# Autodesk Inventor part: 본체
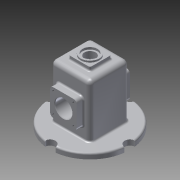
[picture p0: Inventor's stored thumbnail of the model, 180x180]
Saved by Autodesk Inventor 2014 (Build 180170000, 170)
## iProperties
Created: 2018-07
Part Number: 본체
Material: Aluminum 6061
Document SubType Name: Modeling
Designer: kh
Density: 2.71 g/cm^3
Appearance: Aluminum - Flat
Mass: 909.166 g
Surface Area: 1015.89 cm^2
Volume: 335.485 cm^3
Author: kh
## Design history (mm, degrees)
sketch "Sketch1"
  geometry: L1 (0, 0)-(0, 75); L2 (0, 0)-(75, 0); A1 r 75 centre (0, 0) between (0, 75) and (75, 0); 1 further point
  constraints: 4 end point, 2 point on circle, 1 centre point, 1 coincident, 1 perpendicular, 1 vertical
  dimensions: "d0" = 150 diameter of A1
extrude "Extrusion1" new body sketch "Sketch1" distance "d1" = 10; taper "d2" = 0 deg
sketch "Sketch2"
  geometry: L1 (0, 0)-(0, 75); L2 (0, 0)-(75, 0); A1 r 75 centre (0, 0) between (0, 75) and (75, 0) reference; 5 further points
  constraints: 4 end point, 2 point on circle, 1 coincident, 1 perpendicular, 1 vertical, 5 other
  dimensions: "d5" = 360 deg dimension on L1.start point (0, 75) (derived)
hole "Hole1" sketch "Sketch2" at (0, 75), (-75, 0), (0, -75), (75, 0) diameter "d7" = 20; stored, may be unused: countersink angle "d11" = 90 deg, drill point angle "d13" = 118 deg; dims "d8" = 6, "d9" = 4, "d10" = 2, "d12" = 8
sketch "Sketch3"
  geometry: L1 (65, 10)-(65, 0) reference; L2 (65, 0)-(-65, 0) reference; L3 (-65, 0)-(-65, 10) reference; L4 (-65, 10)-(65, 10) reference; L5 (0, 0)-(0, 10); L6 (-37, 0)-(37, 0); L7 (37, 0)-(37, 110); L8 (37, 110)-(-37, 110); L9 (-37, 110)-(-37, 0); L10 (-32, 0)-(32, 0); L11 (32, 0)-(32, 105); L12 (32, 105)-(-32, 105); L13 (-32, 105)-(-32, 0); 1 further point
  constraints: 18 end point, 4 midpoint, 4 parallel, 2 horizontal, 2 perpendicular, 2 other
  dimensions: "d14" = 110 distance between parallel lines of L8 L2; "d15" = 74 distance of L7.end L8.end; "d18" = 5 distance between parallel lines of L8 L12; "d19" = 5 distance between parallel lines of L9 L13
  node "Project Cut Edges1"
extrude "Extrusion2" join sketch "Sketch3" stored distance "d16" = 74; taper "d17" = 0 deg
extrude "Extrusion3" cut sketch "Sketch3" stored distance "d20" = 64; taper "d21" = 0 deg
sketch "Sketch4"
  geometry: L1 (65, 10)-(65, 0) reference; L2 (65, 0)-(32, 0) reference; L3 (32, 0)-(32, 105) reference; L4 (32, 105)-(-32, 105) reference; L5 (-32, 105)-(-32, 0) reference; L6 (-32, 0)-(-65, 0) reference; L7 (-65, 0)-(-65, 10) reference; L8 (-65, 10)-(-37, 10) reference; L9 (-37, 10)-(-37, 110) reference; L10 (-37, 110)-(37, 110) reference; L11 (37, 110)-(37, 10) reference; L12 (37, 10)-(65, 10) reference; L13 (-32, 80)-(-25, 77.452); L14 (-25, 77.452)-(-25, 55); L15 (-25, 55)-(-32, 55); L16 (-32, 55)-(-32, 80); 1 further point
  constraints: 8 end point, 2 perpendicular, 2 point on line, 1 collinear
  dimensions: "d22" = 55 distance from line of L14.end L6; "d23" = 50 diameter of L13.start L15; "d24" = 7 distance between parallel lines of L5 L14; "d25" = 110 deg angle of L5 L13
revolve "Revolution1" sketch "Sketch4" stored, may be unused: angle "d26" = 90 deg
mirror "Mirror1"
sketch "Sketch5"
  geometry: L1 (12, 20)-(62, 20); L2 (62, 20)-(62, 70); L3 (62, 70)-(12, 70); L4 (12, 70)-(12, 20); L5 (12, 20)-(62, 70); L6 (62, 20)-(12, 70); C1 r 25 at (37, 45) reference; 1 further point
  constraints: 12 end point, 2 midpoint, 2 parallel, 1 horizontal, 1 perpendicular
  dimensions: "d27" = 50 distance of L2.end L3.end; "d28" = 50 distance of L3.end L1.start
extrude "Extrusion4" join sketch "Sketch5" distance "d29" = 13; taper "d30" = 0 deg
mirror "Mirror2"
sketch "Sketch6"
  geometry: C1 r 22.452 at (37, 45) reference; C2 r 16 at (37, 45); 1 further point
  constraints: 1 centre point, 1 coincident
  dimensions: "d31" = 32 diameter of C2
extrude "Extrusion5" cut sketch "Sketch6" stored distance "d32" = 13; taper "d33" = 0 deg
sketch "Sketch7"
  geometry: L1 (0, 0)-(74, 0) reference; L2 (74, 74)-(74, 0) reference; L3 (0, 74)-(74, 74) reference; L4 (0, 0)-(0, 74) reference; L5 (17, 17)-(57, 17); L6 (57, 17)-(57, 57); L7 (57, 57)-(17, 57); L8 (17, 57)-(17, 17); L9 (17, 17)-(57, 57); L10 (57, 17)-(17, 57); 1 further point
  constraints: 12 end point, 2 midpoint, 2 parallel, 1 horizontal, 1 perpendicular
  dimensions: "d34" = 40 distance of L6.end L7.end; "d35" = 40 distance of L5.end L6.end
extrude "Extrusion6" join sketch "Sketch7" distance "d36" = 7; taper "d37" = 0 deg
sketch "Sketch8"
  geometry: C1 r 17.5 at (37, 37); 1 further point
  constraints: 1 centre point, 1 coincident
  dimensions: "d38" = 35 diameter of C1
extrude "Extrusion7" join sketch "Sketch8" distance "d39" = 3; taper "d40" = 0 deg
hole "Hole2" diameter "d43" = 21; stored, may be unused: countersink angle "d47" = 90 deg, drill point angle "d49" = 118 deg; dims "d41" = 10, "d42" = 10, "d44" = 6, "d45" = 28, "d46" = 4, "d48" = 8
fillet "Fillet1" dims "d50" = 6
fillet "Fillet2" dims "d51" = 6
sketch "Sketch9"
  geometry: L1 (64.567, -85.815)-(9.433, -85.815); L2 (9.433, -85.815)-(9.433, -74.185); L3 (9.433, -74.185)-(64.567, -74.185); L4 (64.567, -74.185)-(64.567, -85.815); L5 (64.567, -80)-(9.433, -80); L6 (37, -74.185)-(37, -85.815); L7 (19.5, -110)-(54.5, -110) reference; L8 (0, -100)-(0, 0) reference; 2 further points
  constraints: 5 midpoint, 4 end point, 2 other
  dimensions: "d52" = 30 distance from line of L7 point (37, -80); "d53" = 37 distance from line of L8 point (37, -80)
emboss "Emboss1" sketch "Sketch9" dims "d0" = 150, "d54" = 0.5, "d55" = 0
hole "Hole3" diameter "d58" = 3.459; stored, may be unused: countersink angle "d62" = 90 deg, drill point angle "d64" = 118 deg; dims "d56" = 10, "d57" = 10, "d59" = 8, "d60" = 28, "d61" = 4, "d63" = 10
pattern_circular "Circular Pattern1" dims angle "d66" = 360 deg
mirror "Mirror3"
fillet "Fillet3" dims "d68" = 8
fillet "Fillet4" dims "d69" = 8
fillet "Fillet5" dims "d70" = 3
fillet "Fillet6" dims "d71" = 3
fillet "Fillet7" dims "d72" = 3
chamfer "Chamfer1" distance "d73" = 1; stored, may be unused: second distance "d74" = 2, angle "d75" = 45 deg
fillet "Fillet8" dims "d76" = 3
fillet "Fillet9" dims "d77" = 3
fillet "Fillet10" dims "d78" = 3
body "Solid1"
node "Projected Loop1"
node "Projected Loop2"
node "Project Cut Edges2"
